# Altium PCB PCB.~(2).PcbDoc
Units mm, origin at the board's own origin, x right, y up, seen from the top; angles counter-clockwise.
Board outline 77.85 x 88.01 mm, 2 copper layers (Top Layer, Bottom Layer); 33 components, 29 nets, 123 pads, 14 vias.
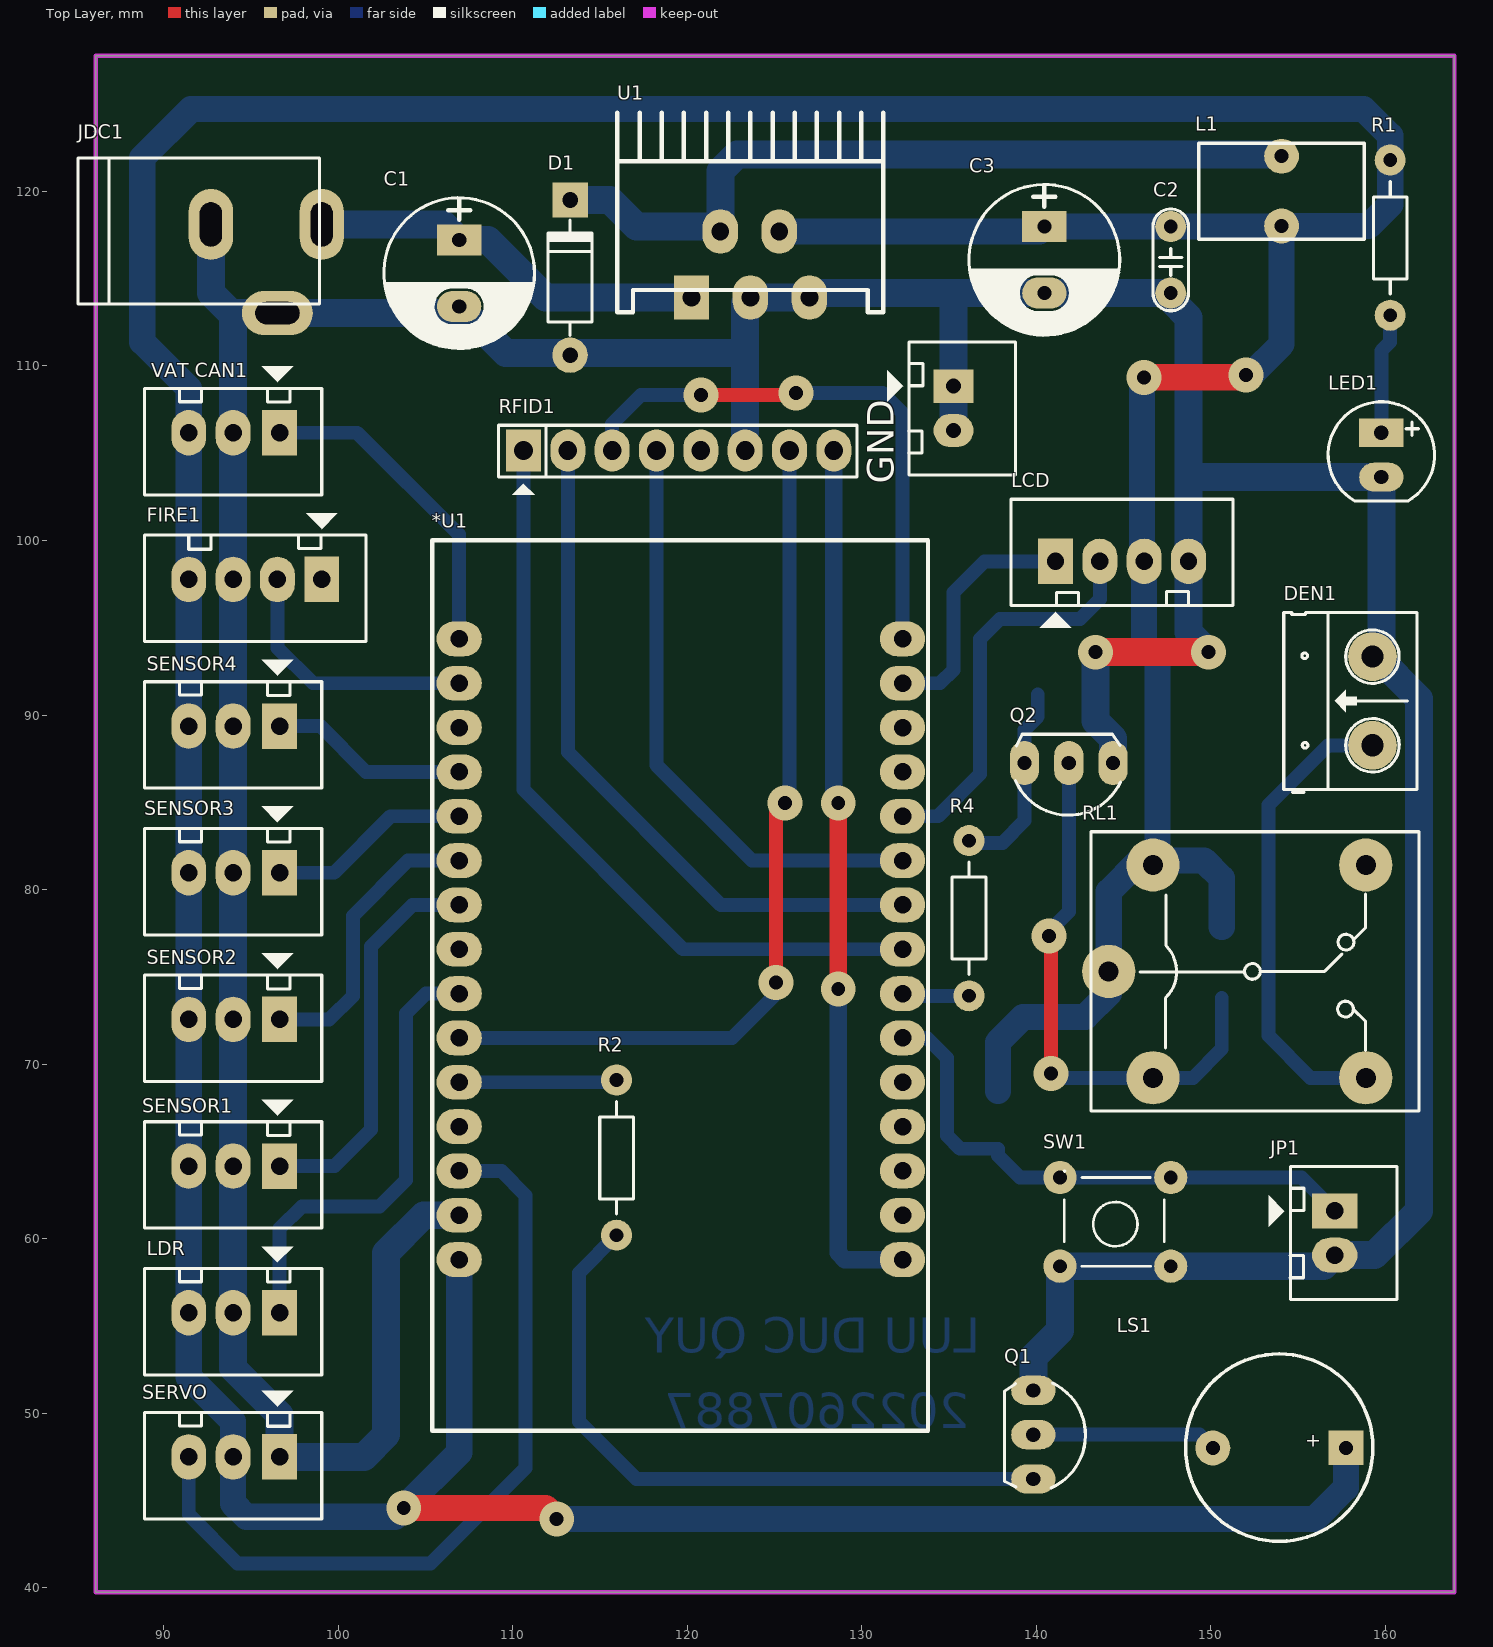
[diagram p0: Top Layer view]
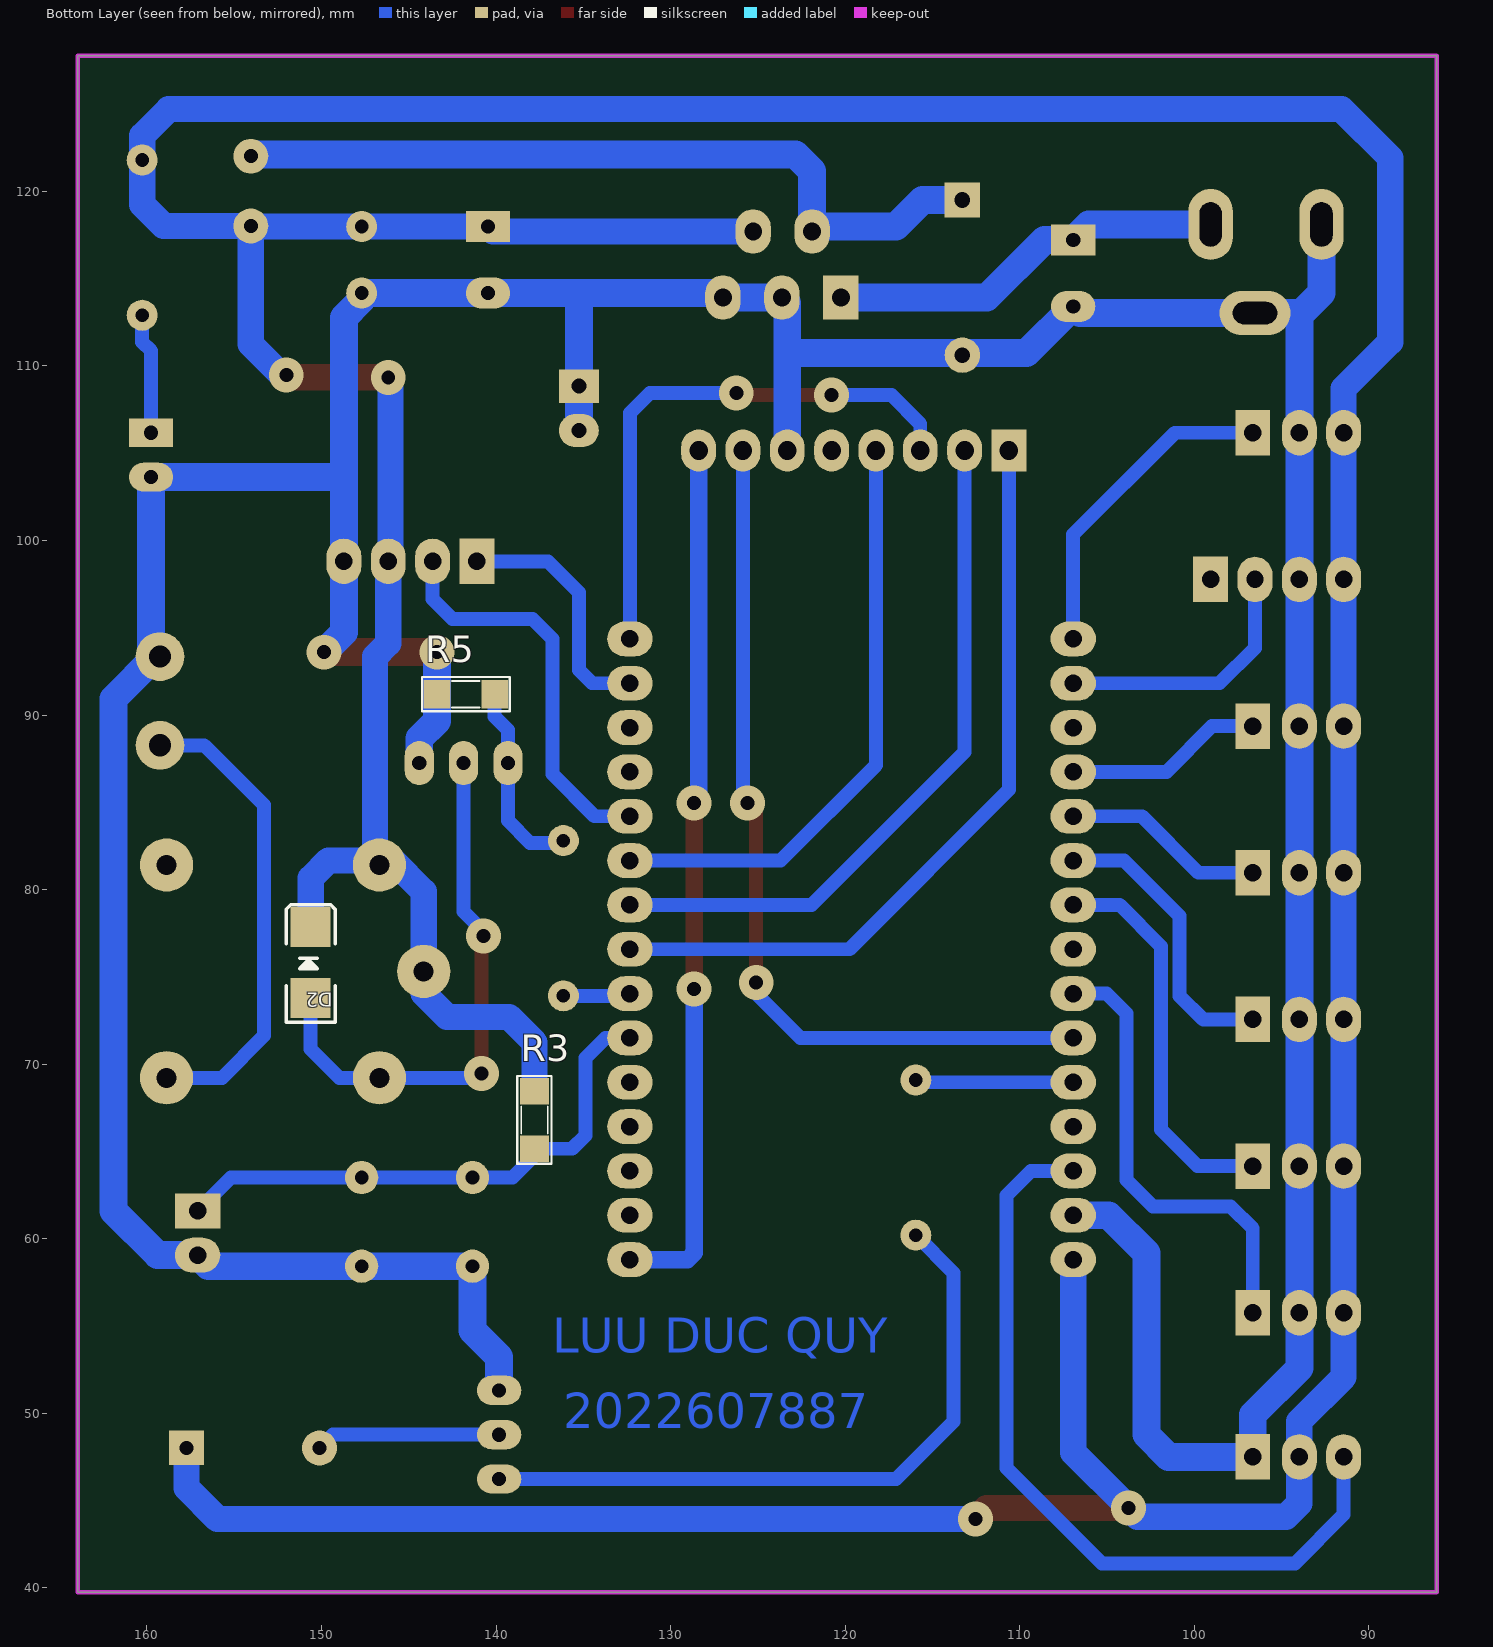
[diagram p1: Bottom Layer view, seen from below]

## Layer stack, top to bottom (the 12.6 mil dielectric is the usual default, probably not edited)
Top Solder: solder mask 0.0102, Solder Resist, Dk 3.5
Top Layer: signal copper 0.0356
Dielectric 1: dielectric 0.32, FR-4, Dk 4.8
Bottom Layer: signal copper 0.0356
Bottom Solder: solder mask 0.0102, Solder Resist, Dk 3.5

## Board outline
86.106,39.751 163.957,39.751 163.957,127.762 86.106,127.762

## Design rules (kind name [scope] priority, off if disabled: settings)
Clearance [All] p1: gap=0.254 ignorepadtopadclearanceinfootprint=FALSE except(0: Arc-Hole Track-Hole SMDPad-Hole THPad-Hole Via-Hole Fill-Hole Poly-Hole Region-Hole Text-Hole)
PolygonConnect [All] p1: connectstyle=Relief reliefconductorwidth=0.254 reliefentries=4 polygonreliefangle="90 Angle" airgapwidth=0.254
RoutingVias [All] p1: holewidth=0.711 width=1.27 viastyle="Through Hole" minholewidth=0.711 minwidth=1.27 maxholewidth=0.711 maxwidth=1.27
SolderMaskExpansion [All] p1: expansion=0.102
Width GND [InNet('GND')] p1: maxlimit=1.6 minlimit=0.254 preferedwidth=1.6
Width 12V [InNet('12V')] p2: maxlimit=1.6 minlimit=0.254 preferedwidth=1.6
Width 3V3 [InNet('3V3')] p3: maxlimit=1 minlimit=0.254 preferedwidth=1
Width 5V [InNet('5V')] p4: maxlimit=3 minlimit=0.254 preferedwidth=1.2
Width NET [All] p5: maxlimit=3 minlimit=0.254 preferedwidth=0.8
30 further rules are at their usual default settings.

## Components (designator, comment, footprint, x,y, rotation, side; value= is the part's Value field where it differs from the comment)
*U1 "*ESP32 module" "ESP32 Module 30PIN" 129.794,58.801 r90 top
C1 "1000uF/16V" CP1.5/3.4 106.934,117.221 r270 top
C2 "103" CN1.5 147.701,114.173 r90 top value=0.01uF
C3 "1000uF/16V" CP1.5/3.4 140.462,117.983 r270 top
D1 "1N4007" D1A 113.284,110.617 r270 top
D2 "1N4007" DIO-SMD-106 150.622,75.819 r270 bottom
DEN1 "Header 2" HED2 159.258,88.265 r90 top
FIRE1 "JP4" CON4 99.06,97.769 r180 top value="Connector 4"
GND "JP2" CON2#1 135.255,108.839 r270 top value="Connector 2"
JDC1 "Jac DC" DC0 95.885,115.57 r0 top
JP1 "JP2" CON2#2 157.099,61.595 r270 top value="Connector 2"
L1 "L-DIP-1" L-DIP-M-9.5x5.5 154.051,120.015 r270 top value="150 mH"
LCD "JP4" CON4 141.097,98.806 r0 top value="Connector 4"
LDR "JP3" CON3 96.52,55.753 r180 top value="Connector 3"
LED1 "LED" LED-5-Green 159.766,106.172 r270 top value="LED 3 ly Single Colour"
LS1 "Speaker" SPEAKER 157.734,48.019 r180 top
Q1 "C1815" QTO-92 139.827,48.768 r270 top
Q2 "C1815" QTO-92 141.859,87.249 r180 top
R1 "1k" R1/4W 160.274,121.793 r270 top value="R1/4W - 1K"
R2 "1k" R1/4W 115.951,69.088 r270 top value="R1/4W - 1K"
R3 "10k" SM-RES-1206 137.795,65.151 r90 bottom value="R1/4W - 1K"
R4 "1k" R1/4W 136.144,73.914 r90 top value="R1/4W - 1K"
R5 "10k" SM-RES-1206 143.383,91.186 r180 bottom value="R1/4W - 1K"
RFID1 "RFID RC522" JP8 110.617,105.156 r0 top
RL1 "Relay 10A/12V" RL_SPDT_10A 144.145,75.311 r0 top value="Relay SPDT, 10A, 12V"
SENSOR1 "JP3" CON3 96.52,64.156 r180 top value="Connector 3"
SENSOR2 "JP3" CON3 96.52,72.559 r180 top value="Connector 3"
SENSOR3 "JP3" CON3 96.52,80.962 r180 top value="Connector 3"
SENSOR4 "JP3" CON3 96.52,89.366 r180 top value="Connector 3"
SERVO "JP3" CON3 96.52,47.498 r180 top value="Connector 3"
SW1 "SW" SW4 147.701,58.42 r180 top value="Button chip 4 pin"
U1 "LM2576" DIP5-T 123.596,118.161 r0 top
"VAT CAN1" "JP3" CON3 96.52,106.172 r180 top value="Connector 3"

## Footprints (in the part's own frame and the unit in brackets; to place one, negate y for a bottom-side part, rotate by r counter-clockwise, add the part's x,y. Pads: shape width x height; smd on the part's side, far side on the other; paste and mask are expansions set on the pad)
CN1.5 [mil]
  round 70 hole 31: 1(0,0) 2(150,0)
  silkscreen extent -40,-40 190,40, body extent -40,-33 190,33, height 235
CON2#1 [mil] "CON2"
  rect 75x90 hole 34: 1(0,0)
  oval 75x90 hole 34: 2(100,0)
  silkscreen extent -100,-150 200,140, body extent -68,-70 168,107, height 236
CON2#2 [mil] "CON2"
  rect 78.74x102.36 hole 39.37: 1(0,0)
  oval 78.74x102.36 hole 39.37: 2(100,0)
  silkscreen extent -100,-150 200,140, body extent -68,-70 168,107, height 236
CON3 [mm] "CON 3"
  rect 2x2.6 hole 1: 1(-0.127,0)
  oval 2x2.6 hole 1: 2(2.54,0) 3(5.08,0)
  silkscreen extent -2.54,-3.8 7.62,3.56, body extent -2.41,-2.29 7.49,3.46, height 7
CON4 [mm] "CON4"
  rect 2x2.6 hole 1: 1(0,0)
  oval 2x2.6 hole 1: 2(2.54,0) 3(5.08,0) 4(7.62,0)
  silkscreen extent -2.54,-3.8 10.16,3.56, body extent -2.29,-2.29 10.11,3.46, height 7
CP1.5/3.4 [mil] "Tu hoa 220->470uF,16V, 470uF/16V,25V"
  rect 70x100 hole 32: 1(0,0)
  oval 70x100 hole 32: 2(150,0)
  silkscreen extent -95,-170 245,170, body extent -85,-157 230,157, height 446
D1A [mil] "Diode 1A, W 100mil, L 350mil"
  round 80 hole 35: 1(0,0)
  rect 80x80 hole 35: 2(-350,0)
  silkscreen extent -305,-50 -45,50, body extent -386,-33 34,36, height 84
DC0 [mil] "Jac DC input"
  oval 100x160 hole 50 slot 100 at 90 deg: 1(125,100) 2(-125,100)
  oval 160x100 hole 50 slot 100 at 0 deg: 3(25,-100)
  silkscreen extent -425,-80 120,250, body extent -410,-105 134,269, height 434
DIO-SMD-106 [mil]
  rect 90x90.55 smd: 1(80,0) 2(-80,0)
  silkscreen extent -130,-55 135,55, body extent -99,-50 106,52, height 95
DIP5-T [mil]
  rect 80x100 hole 40: 1(-132,-167.09)
  oval 80x100 hole 40: 2(-67,-18) 3(1,-167) 4(66,-18) 5(134,-167)
  round 0 all layers, no hole: ""(1,100)
  silkscreen extent -299,-200 301,250, body extent -199,-175 201,150, height 859
"ESP32 Module 30PIN" [mm]
  oval 2x2.6 hole 1 unplated: 1(0,-2.54) 2(2.54,-2.54) 3(5.08,-2.54) 4(7.62,-2.54) 5(10.16,-2.54) 6(12.7,-2.54) 7(15.24,-2.54) 8(17.78,-2.54) 9(20.32,-2.54) 10(22.86,-2.54) 11(25.4,-2.54) 12(27.94,-2.54) 13(30.48,-2.54) 14(33.02,-2.54) 15(35.56,-2.54) 16(35.56,22.86) 17(33.02,22.86) 18(30.48,22.86) 19(27.94,22.86) 20(25.4,22.86) 21(22.86,22.86) 22(20.32,22.86) 23(17.78,22.86) 24(15.24,22.86) 25(12.7,22.86) 26(10.16,22.86) 27(7.62,22.86) 28(5.08,22.86) 29(2.54,22.86) 30(0,22.86)
  silkscreen extent -9.8,-4 41.2,24.4, body extent -9.9,-4.15 41.03,24.35, height 10.2
HED2 [mil] "Header 2, 2 pin, hight 300mil, Pin to Pin 200, Colour Green"
  round 110 hole 50: 1(0,0) 2(200,0)
  silkscreen extent -106,-100 300,200, body extent -92,-140 302,155, height 394
JP8 [mm] "JP8"
  rect 2x2.4 hole 1.067: 1(0,0)
  oval 2x2.4 hole 1.067: 2(2.54,0) 3(5.08,0) 4(7.62,0) 5(10.16,0) 6(12.7,0) 7(15.24,0) 8(17.78,0)
  silkscreen extent -1.42,-2.54 19.1,1.45, body extent -1.22,-1.27 19,1.23, height 8.22
L-DIP-M-9.5x5.5 [mm] "Body 9.5x5.5mm, 2 leads"
  round 2 hole 0.8: 1(-2,0) 2(2,0)
  silkscreen extent -2.75,-4.75 2.75,4.75, body extent -2.57,-5.05 2.57,5.05, height 10.07
LED-5-Green [mil] "LED 2 PIN, 5 ly , Only colour,pin to pin 100mil"
  rect 65x100 hole 32: 1(0,0)
  oval 65x100 hole 32: 2(100,0)
  silkscreen extent -70,-120 154,120, body extent -69,-120 145,117, height 339
QTO-92 [mil] "TO-92"
  oval 66x100 hole 32: 1(-100,0) 2(0,0) 3(100,0)
  silkscreen extent -117,-65 120,118, body extent -109,-66 109,95, height 245
R1/4W [mil] "R 1/4W, 2 Pin, 350mil"
  round 70 hole 31: 1(0,0) 2(350,0)
  silkscreen extent 48,-38 302,38, body extent -40,-47 386,47, height 111
RL_SPDT_10A [mil] "Relay SPDT, 5 pin, 10A,W 650mil, L 800mil, H 800mil"
  round 120 hole 45: 1(0,0) 2(580,240) 3(580,-240) 4(100,-240) 5(100,240)
  silkscreen extent -40,-315 700,315, body extent -46,-304 706,306, height 602
SM-RES-1206 [mil]
  rect 60x65 smd: 1(0,0) 2(130,0)
  silkscreen extent -34,-38 164,39, body extent 2,-31 128,31, height 40
SPEAKER [mm]
  rect 2x2 hole 0.8: 1(0,0)
  round 2 hole 0.8: 2(7.62,0.013)
  silkscreen extent -1.55,-5.38 9.18,5.36, body extent -2.22,-6 13.24,6, height 4.5
SW4 [mil] "SW button 4pin, 250 x250 mil"
  round 75 hole 31: 1(0,0) 2(250,-200) 3(250,0) 4(0,-200)
  silkscreen extent 15,-215 240,0, body extent -36,-220 276,24, height 276

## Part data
*U1: library part "ESP32 module"
C1 C3: library part CP4, "Cap 1000uF/16V - 220uF/50V"
C2: library part CN1.5, "Cap np 682pF => 104pF"
D1 D2: library part D1A, "Diode 1A"
DEN1: library part Hed2, "Header 2 (Green)"
FIRE1 LCD: library part Con4, "Connector 4"
GND JP1: library part Con2, "Connector 2"
JDC1: library part DCIN, "Jac DC input"
L1: "Inductor"
LDR SENSOR1 SENSOR2 SENSOR3 SENSOR4 SERVO "VAT CAN1": library part Con3, "Connector 3"
LED1: "LED Single colour Green and Red"
LS1: "Loudspeaker"
Q1 Q2: "NPN 600mW, ECB"
R1 R2 R4: library part R1/4W, "Resistor 1/4W"
R3 R5: library part R, "Resistor 1/4W"
RL1: library part "Relay 1", "Relay SPDT,10A - 12VDC 5 Pin"
SW1: library part SW4, "Switch button 4 pin"
U1: Max Input Voltage="12 V", Max Output Current="3 (6.0 peak) A", Max Output Voltage=mV, Temperature Range="-40 to +125 degC"

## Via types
v1: diameter 2, hole 0.8, Top Layer to Bottom Layer, 14 vias

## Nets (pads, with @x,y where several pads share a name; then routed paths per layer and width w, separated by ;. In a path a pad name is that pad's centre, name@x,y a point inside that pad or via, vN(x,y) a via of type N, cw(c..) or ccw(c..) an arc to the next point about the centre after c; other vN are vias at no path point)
3V3: *U1.1 RFID1.8 | length 48.9
  Top Layer w1: v1(128.651,74.295) v1(128.651,84.963)
  Bottom Layer w1: v1@128.397,85.344 RFID1.8 ; v1@128.651,73.787 128.651,59.182 129.032,58.801 *U1.1
5V: "VAT CAN1.3" *U1.30 C2.2 C3.1 D2.2 FIRE1.4 L1.2 LCD.3 LDR.3 LS1.1 R1.1 R3.2 RL1.1 RL1.5 SENSOR1.3 SENSOR2.3 SENSOR3.3 SENSOR4.3 SERVO.2 U1.4 | length 344.3
  Top Layer w1.5: v1(103.759,44.577) 111.887,44.577 v1(112.522,43.942) ; v1(146.177,109.347) 151.892,109.347 v1(152.019,109.474)
  Bottom Layer w1.5: *U1.30 106.934,47.752 v1(103.759,44.577) 103.251,44.069 94.742,44.069 93.98,44.831 SERVO.2 93.98,49.53 91.44,52.07 LDR.3 SENSOR1.3 SENSOR2.3 SENSOR3.3 SENSOR4.3 FIRE1.4 91.44,106.172 91.44,108.712 88.773,111.379 88.773,121.92 91.567,124.714 158.75,124.714 160.274,123.19 R1.1 160.274,119.253 159.036,118.015 L1.2 ; v1@112.649,43.942 155.956,43.942 157.734,45.72 LS1.1 ; U1.4 140.183,117.704 C3.1 C2.2 154.019,117.983 L1.2 ; R3.2 137.795,71.247 139.255,72.707 142.811,72.707 144.145,74.041 RL1.1 144.145,79.883 145.923,81.661 RL1.5@146.939,81.661 ; v1@146.047,108.715 146.047,98.936 LCD.3 146.177,94.107 146.939,93.345 RL1.5@146.939,81.661 ; D2.2 150.622,80.645 149.606,81.661 RL1.5@146.939,81.661 ; v1@152.273,109.474 154.051,111.252 L1.2
12V: C1.1 JDC1.1 U1.1 | length 22.9
  Bottom Layer w1.6: JDC1.1 106.045,118.11 C1.1 108.585,117.221 111.889,113.917 U1.1
Buzzer: *U1.26 R2.1 | length 9.1
  Bottom Layer w0.8: *U1.26 115.824,68.961 R2.1
GND: "VAT CAN1.2" *U1.29 C1.2 C2.1 C3.2 D1.1 DEN1.2 FIRE1.3 GND.1 GND.2 JDC1.2 JDC1.3 JP1.2 LCD.4 LDR.2 LED1.2 Q1.1 Q2.1 R5.1 RFID1.6 SENSOR1.2 SENSOR2.2 SENSOR3.2 SENSOR4.2 SERVO.1 SW1.1 SW1.3 U1.3 U1.5 | length 285.1
  Top Layer w1.6: v1(143.383,93.599) v1(149.86,93.599)
  Bottom Layer w1.6: JDC1.2 92.71,114.173 93.853,113.03 94.234,113.03 ; *U1.29 104.902,61.341 102.743,59.182 102.743,48.768 101.473,47.498 SERVO.1 96.647,49.911 93.98,52.578 LDR.2 SENSOR1.2 SENSOR2.2 SENSOR3.2 SENSOR4.2 FIRE1.3 93.98,106.172 93.98,112.776 94.234,113.03 ; RFID1.6 123.317,110.744 ; GND.2 GND.1 135.255,114.173 ; Q1.1 139.827,53.213 141.351,54.737 SW1.3 SW1.1 156.464,58.42 JP1.2 159.385,59.055 161.925,61.595 161.925,90.932 159.512,93.345 DEN1.2 159.766,93.853 LED1.2 148.971,103.632 148.717,103.378 ; v1(143.383,93.599) R5.1 143.383,89.662 144.399,88.646 Q2.1 ; v1(149.86,93.599) 148.717,94.742 LCD.4 148.717,103.378 ; 94.234,113.03 JDC1.3 106.553,113.03 C1.2 109.601,110.744 123.317,110.744 ; 123.317,110.744 123.317,113.614 U1.3 U1.5 127.254,114.173 135.255,114.173 ; 135.255,114.173 C3.2 C2.1 147.701,113.792 148.717,112.776 148.717,103.378
LCD_SCL: *U1.14 LCD.1 | length 14.3
  Bottom Layer w0.8: *U1.14 134.493,91.821 135.255,92.583 135.255,97.028 137.033,98.806 LCD.1
LCD_SDA: *U1.11 LCD.2 | length 23.2
  Bottom Layer w0.8: *U1.11 134.366,84.201 136.779,86.614 136.779,94.361 137.922,95.504 142.494,95.504 143.637,96.647 LCD.2
NetD1_2: D1.2 L1.1 U1.2 | length 45.5
  Bottom Layer w1.6: D1.2 115.57,119.507 117.094,117.983 121.615,117.983 U1.2 121.895,121.158 122.841,122.105 154.051,122.105 L1.1
NetD2_1: D2.1 Q2.2 RL1.4 | length 31.8
  Top Layer w0.8: v1(140.716,77.343) 140.843,77.216 v1(140.843,69.469)
  Bottom Layer w0.8: v1@140.335,77.216 141.859,78.74 Q2.2 ; v1@140.97,69.215 RL1.4 148.971,69.215 150.622,70.866 D2.1
NetDEN1_1: DEN1.1 RL1.3 | length 27.2
  Bottom Layer w0.8: RL1.3 155.702,69.215 153.289,71.628 153.289,84.836 156.718,88.265 DEN1.1
NetLED1_1: LED1.1 R1.2 | length 6.9
  Bottom Layer w0.8: LED1.1 159.766,110.871 160.274,111.379 R1.2
NetLS1_2: LS1.2 Q1.2 | length 10.6
  Bottom Layer w0.8: Q1.2 149.352,48.768 LS1.2
NetQ1_3: Q1.3 R2.2 | length 39
  Bottom Layer w0.8: R2.2 113.792,58.039 113.792,49.53 117.094,46.228 Q1.3
NetQ2_3: Q2.3 R4.2 R5.2 | length 11.3
  Bottom Layer w0.8: R4.2 136.271,82.677 138.049,82.677 139.319,83.947 Q2.3 139.319,89.154 140.081,89.916 R5.2
"PIN_BTN MANUAL": *U1.6 JP1.1 R3.1 SW1.2 SW1.4 | length 31.7
  Bottom Layer w0.8: *U1.6 133.731,71.501 134.874,70.358 134.874,65.913 135.636,65.151 R3.1 137.795,64.77 139.065,63.5 SW1.2 SW1.4 155.194,63.5 JP1.1
PIN_FIRE: *U1.17 FIRE1.2 | length 15.2
  Bottom Layer w0.8: FIRE1.2 96.52,93.853 98.552,91.821 *U1.17
PIN_LIGHT: *U1.24 LDR.1 | length 26.3
  Bottom Layer w0.8: LDR.1 96.647,60.579 97.917,61.849 102.362,61.849 103.886,63.373 103.886,72.898 105.029,74.041 *U1.24
PIN_RELAY: *U1.7 R4.1 | length 3.9
  Bottom Layer w0.8: *U1.7 132.461,73.914 R4.1
PIN_S1: *U1.22 SENSOR1.1 | length 22.6
  Bottom Layer w0.8: SENSOR1.1 99.801,64.156 101.892,66.247 101.892,76.746 104.267,79.121 *U1.22
PIN_S2: *U1.21 SENSOR2.1 | length 16.7
  Bottom Layer w0.8: SENSOR2.1 99.483,72.559 100.838,73.914 100.838,78.486 104.013,81.661 *U1.21
PIN_S3: *U1.20 SENSOR3.1 | length 11.6
  Bottom Layer w0.8: SENSOR3.1 99.758,80.962 102.997,84.201 *U1.20
PIN_S4: *U1.19 SENSOR4.1 | length 11.4
  Bottom Layer w0.8: SENSOR4.1 98.975,89.366 101.6,86.741 *U1.19
PIN_VATCAN: "VAT CAN1.1" *U1.16 | length 18.7
  Bottom Layer w0.8: 96.647,106.172 101.092,106.172 106.934,100.33 *U1.16
RFID_MISO: *U1.10 RFID1.4 | length 34.4
  Bottom Layer w0.8: RFID1.4 118.237,87.122 123.698,81.661 *U1.10
RFID_MOSI: *U1.15 RFID1.3 | length 32.3
  Top Layer w0.8: v1(120.777,108.331) 126.111,108.331 v1(126.238,108.458)
  Bottom Layer w0.8: RFID1.3 115.697,106.68 117.348,108.331 v1(120.777,108.331) ; v1(126.238,108.458) 131.191,108.458 132.334,107.315 *U1.15
RFID_RST: *U1.25 RFID1.7 | length 50.7
  Top Layer w0.8: v1(125.095,74.676) 125.095,84.455 v1(125.603,84.963)
  Bottom Layer w0.8: *U1.25 122.555,71.501 124.968,73.914 v1@124.968,74.676 ; v1@125.857,84.709 RFID1.7
RFID_SCK: *U1.9 RFID1.2 | length 40.1
  Bottom Layer w0.8: RFID1.2 113.157,87.884 121.92,79.121 *U1.9
RFID_SS: *U1.8 RFID1.1 | length 44.9
  Bottom Layer w0.8: RFID1.1 110.617,85.725 119.761,76.581 *U1.8
servo: *U1.28 SERVO.3 | length 46
  Bottom Layer w0.8: SERVO.3 91.44,44.196 94.234,41.402 105.283,41.402 110.744,46.863 110.744,62.484 109.347,63.881 *U1.28
pads on no net: *U1.2 *U1.3 *U1.4 *U1.5 *U1.12 *U1.13 *U1.18 *U1.23 *U1.27 FIRE1.1 RFID1.5 RL1.2 U1.

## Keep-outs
Keep-Out Layer:
  the board outline again, w0.254

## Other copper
Bottom Layer:
  text "LUU DUC QUY" at 136.779,53.467 h2
  text "2022607887" at 136.144,49.149 h2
